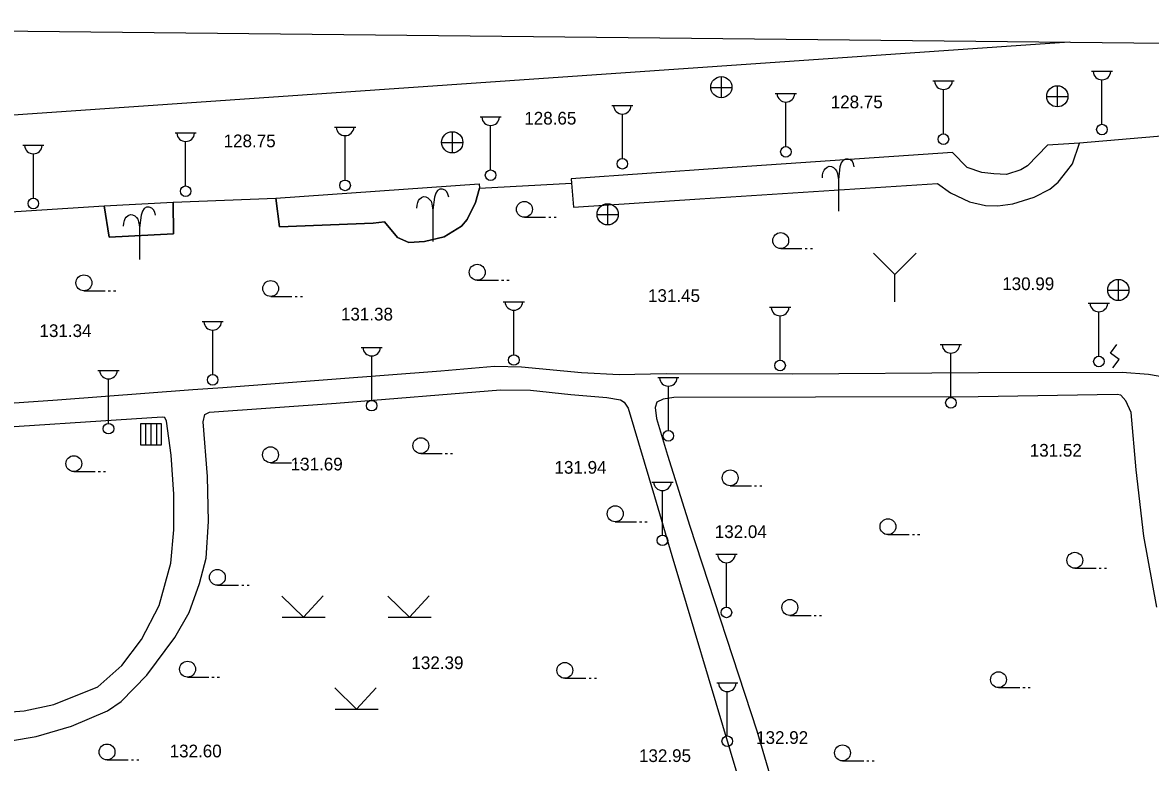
# Model space of a CAD drawing. Extents: x 419101 to 420177, y 4451541 to 4452254.
# Drawn here: x 419185.8 to 419292.2, y 4452175.9 to 4452245.8 of the extents above; entities that cross this region are included whole.
import ezdxf

# ---------------------------------------------------------------- set-up
doc = ezdxf.new("R2010")
doc.units = 0
doc.layers.add('0_ÖNERİ_LEJAND', color=7, linetype='Continuous')
doc.layers.add('3_HALİHAZIR', color=7, linetype='Continuous')

msp = doc.modelspace()

# ---------------------------------------------------------------- linework, layer by layer
at = {"layer": '0_ÖNERİ_LEJAND'}
msp.add_lwpolyline([(419108.72, 4452245.78), (420173.1, 4452234.54), (420165.77, 4451540.51), (419101.3, 4451551.75)], close=True, dxfattribs=at)
at = {"layer": '3_HALİHAZIR'}
for p, q in [((419251.71, 4452238.67), (419251.71, 4452240.67)), ((419271.64, 4452240.27), (419273.64, 4452240.27)), ((419286.6, 4452241.18), (419288.6, 4452241.18)), ((419287.6, 4452236.18), (419287.6, 4452240.37)), ((419250.69, 4452239.66), (419252.69, 4452239.66)), ((419272.64, 4452235.27), (419272.64, 4452239.46)), ((419283.41, 4452237.81), (419283.41, 4452239.81)), ((419256.78, 4452239.08), (419258.78, 4452239.08)), ((419257.78, 4452234.08), (419257.78, 4452238.27)), ((419282.39, 4452238.8), (419284.39, 4452238.8)), ((419241.35, 4452237.95), (419243.35, 4452237.95)), ((419242.35, 4452232.95), (419242.35, 4452237.15)), ((419215.19, 4452235.91), (419217.19, 4452235.91)), ((419228.92, 4452236.87), (419230.92, 4452236.87)), ((419229.92, 4452231.87), (419229.92, 4452236.06)), ((419200.15, 4452235.36), (419202.15, 4452235.36)), ((419216.19, 4452230.91), (419216.19, 4452235.11)), ((419226.31, 4452233.46), (419226.31, 4452235.46)), ((419185.78, 4452234.2), (419187.78, 4452234.2)), ((419201.15, 4452230.36), (419201.15, 4452234.56)), ((419225.29, 4452234.45), (419227.29, 4452234.45)), ((419186.78, 4452229.2), (419186.78, 4452233.4)), ((419240.98, 4452226.67), (419240.98, 4452228.67)), ((419233.11, 4452227.4), (419235.11, 4452227.4)), ((419235.41, 4452227.4), (419235.61, 4452227.4)), ((419235.91, 4452227.4), (419236.11, 4452227.4)), ((419239.96, 4452227.66), (419241.96, 4452227.66)), ((419257.29, 4452224.45), (419259.29, 4452224.45)), ((419259.59, 4452224.45), (419259.79, 4452224.45)), ((419260.09, 4452224.45), (419260.29, 4452224.45)), ((419268.06, 4452222.01), (419266.06, 4452224.01)), ((419268.06, 4452222.01), (419270.07, 4452224.01)), ((419228.66, 4452221.46), (419230.66, 4452221.46)), ((419230.96, 4452221.46), (419231.16, 4452221.46)), ((419231.46, 4452221.46), (419231.66, 4452221.46)), ((419268.06, 4452219.42), (419268.06, 4452222.01)), ((419289.16, 4452219.53), (419289.16, 4452221.53)), ((419191.55, 4452220.46), (419193.55, 4452220.46)), ((419193.85, 4452220.46), (419194.05, 4452220.46)), ((419194.35, 4452220.46), (419194.55, 4452220.46)), ((419209.17, 4452219.93), (419211.17, 4452219.93)), ((419211.47, 4452219.93), (419211.67, 4452219.93)), ((419211.97, 4452219.93), (419212.17, 4452219.93)), ((419288.14, 4452220.52), (419290.14, 4452220.52)), ((419231.11, 4452219.43), (419233.11, 4452219.43)), ((419256.23, 4452218.91), (419258.23, 4452218.91)), ((419286.31, 4452219.29), (419288.31, 4452219.29)), ((419232.11, 4452214.43), (419232.11, 4452218.63)), ((419257.23, 4452213.91), (419257.23, 4452218.1)), ((419287.31, 4452214.29), (419287.31, 4452218.48)), ((419202.7, 4452217.56), (419204.7, 4452217.56)), ((419203.7, 4452212.56), (419203.7, 4452216.75)), ((419217.7, 4452215.12), (419219.7, 4452215.12)), ((419272.35, 4452215.39), (419274.35, 4452215.39)), ((419218.7, 4452210.12), (419218.7, 4452214.31)), ((419273.35, 4452210.39), (419273.35, 4452214.58)), ((419192.87, 4452212.95), (419194.87, 4452212.95)), ((419193.87, 4452207.95), (419193.87, 4452212.15)), ((419245.69, 4452212.27), (419247.69, 4452212.27)), ((419246.69, 4452207.27), (419246.69, 4452211.46)), ((419198.88, 4452207.92), (419196.88, 4452207.92)), ((419196.88, 4452207.92), (419196.88, 4452205.92)), ((419198.88, 4452207.92), (419196.88, 4452207.92)), ((419196.88, 4452207.92), (419196.88, 4452205.92)), ((419197.39, 4452205.92), (419197.39, 4452207.92)), ((419197.88, 4452205.92), (419197.88, 4452207.92)), ((419198.43, 4452205.92), (419198.43, 4452207.92)), ((419198.88, 4452205.92), (419198.88, 4452207.92)), ((419198.88, 4452205.92), (419198.88, 4452207.92)), ((419196.88, 4452205.92), (419198.88, 4452205.92)), ((419196.88, 4452205.92), (419198.88, 4452205.92)), ((419223.34, 4452205.1), (419225.34, 4452205.1)), ((419225.64, 4452205.1), (419225.84, 4452205.1)), ((419226.14, 4452205.1), (419226.34, 4452205.1)), ((419209.15, 4452204.24), (419211.15, 4452204.24)), ((419211.45, 4452204.24), (419211.65, 4452204.24)), ((419211.95, 4452204.24), (419212.15, 4452204.24)), ((419190.6, 4452203.4), (419192.6, 4452203.4)), ((419192.9, 4452203.4), (419193.1, 4452203.4)), ((419193.4, 4452203.4), (419193.6, 4452203.4)), ((419245.13, 4452202.41), (419247.13, 4452202.41)), ((419252.52, 4452202.06), (419254.52, 4452202.06)), ((419254.82, 4452202.06), (419255.02, 4452202.06)), ((419255.32, 4452202.06), (419255.52, 4452202.06)), ((419246.13, 4452197.41), (419246.13, 4452201.6)), ((419241.68, 4452198.67), (419243.68, 4452198.67)), ((419243.98, 4452198.67), (419244.18, 4452198.67)), ((419244.48, 4452198.67), (419244.68, 4452198.67)), ((419267.41, 4452197.45), (419269.41, 4452197.45)), ((419269.71, 4452197.45), (419269.91, 4452197.45)), ((419270.21, 4452197.45), (419270.41, 4452197.45)), ((419251.17, 4452195.61), (419253.17, 4452195.61)), ((419252.17, 4452190.61), (419252.17, 4452194.81)), ((419285.04, 4452194.28), (419287.04, 4452194.28)), ((419287.34, 4452194.28), (419287.54, 4452194.28)), ((419287.84, 4452194.28), (419288.04, 4452194.28)), ((419204.14, 4452192.67), (419206.14, 4452192.67)), ((419206.44, 4452192.67), (419206.64, 4452192.67)), ((419206.94, 4452192.67), (419207.14, 4452192.67)), ((419212.28, 4452189.65), (419210.22, 4452191.64)), ((419212.28, 4452189.65), (419214.13, 4452191.66)), ((419222.28, 4452189.65), (419220.22, 4452191.64)), ((419222.28, 4452189.65), (419224.13, 4452191.66)), ((419210.26, 4452189.65), (419214.3, 4452189.65)), ((419220.26, 4452189.65), (419224.3, 4452189.65)), ((419258.15, 4452189.83), (419260.15, 4452189.83)), ((419260.45, 4452189.83), (419260.65, 4452189.83)), ((419260.95, 4452189.83), (419261.15, 4452189.83)), ((419201.33, 4452184), (419203.33, 4452184)), ((419203.63, 4452184), (419203.83, 4452184)), ((419204.13, 4452184), (419204.33, 4452184)), ((419236.92, 4452183.89), (419238.92, 4452183.89)), ((419239.22, 4452183.89), (419239.42, 4452183.89)), ((419239.72, 4452183.89), (419239.92, 4452183.89)), ((419217.28, 4452180.99), (419215.22, 4452182.98)), ((419217.28, 4452180.99), (419219.13, 4452183)), ((419251.25, 4452183.45), (419253.25, 4452183.45)), ((419277.84, 4452183.01), (419279.84, 4452183.01)), ((419280.14, 4452183.01), (419280.34, 4452183.01)), ((419280.64, 4452183.01), (419280.84, 4452183.01)), ((419252.25, 4452178.45), (419252.25, 4452182.64)), ((419215.26, 4452180.99), (419219.3, 4452180.99)), ((419193.73, 4452176.19), (419195.73, 4452176.19)), ((419196.03, 4452176.19), (419196.23, 4452176.19)), ((419196.53, 4452176.19), (419196.73, 4452176.19)), ((419263.12, 4452176.1), (419265.12, 4452176.1)), ((419265.42, 4452176.1), (419265.62, 4452176.1)), ((419265.92, 4452176.1), (419266.12, 4452176.1))]:
    msp.add_line(p, q, dxfattribs=at)
for points in [[(419284.52, 4452243.92), (419146.62, 4452234.38)], [(419293.94, 4452235.13), (419285.48, 4452234.41)], [(419209.65, 4452229.19), (419210, 4452226.5), (419218.83, 4452226.84), (419219.9, 4452226.98), (419221.14, 4452225.48), (419222.21, 4452225.03), (419223.68, 4452225.12), (419225.53, 4452225.54), (419227.18, 4452226.57), (419227.72, 4452227.2), (419228.51, 4452228.8), (419228.87, 4452230.15), (419237.55, 4452230.63), (419237.74, 4452228.37), (419249.66, 4452229.13), (419272.09, 4452230.59), (419273.31, 4452229.72), (419275.09, 4452228.85), (419276.6, 4452228.5), (419277.77, 4452228.47), (419279.2, 4452228.67), (419281.2, 4452229.3), (419282.69, 4452230.04), (419283.46, 4452230.72), (419284.3, 4452231.75), (419284.82, 4452232.44), (419285.48, 4452234.41)], [(419264.23, 4452232.15), (419264.16, 4452232.45), (419264.05, 4452232.67), (419263.89, 4452232.83), (419263.64, 4452232.9), (419263.4, 4452232.9), (419263.17, 4452232.79), (419263.01, 4452232.55), (419262.88, 4452232.17), (419262.73, 4452230.97)], [(419261.23, 4452231.11), (419261.24, 4452231.4), (419261.3, 4452231.67), (419261.38, 4452231.84), (419261.47, 4452231.97), (419261.66, 4452232.13), (419261.86, 4452232.22), (419262.07, 4452232.19), (419262.27, 4452232.1), (419262.43, 4452231.95), (419262.56, 4452231.79), (419262.64, 4452231.53), (419262.68, 4452231.3), (419262.73, 4452230.97), (419262.73, 4452227.97)], [(419225.97, 4452229.29), (419225.9, 4452229.59), (419225.79, 4452229.81), (419225.63, 4452229.97), (419225.38, 4452230.04), (419225.14, 4452230.04), (419224.91, 4452229.93), (419224.75, 4452229.69), (419224.62, 4452229.31), (419224.47, 4452228.11)], [(419146.52, 4452225.31), (419152.71, 4452225.75), (419166.47, 4452226.75), (419193.47, 4452228.47)], [(419193.47, 4452228.47), (419193.93, 4452225.53), (419199.99, 4452225.83), (419199.98, 4452228.83)], [(419199.98, 4452228.83), (419209.65, 4452229.19)], [(419222.97, 4452228.25), (419222.98, 4452228.54), (419223.04, 4452228.81), (419223.12, 4452228.98), (419223.21, 4452229.11), (419223.4, 4452229.27), (419223.6, 4452229.36), (419223.81, 4452229.33), (419224.01, 4452229.24), (419224.17, 4452229.09), (419224.3, 4452228.93), (419224.38, 4452228.67), (419224.42, 4452228.44), (419224.47, 4452228.11), (419224.47, 4452225.11)], [(419195.3, 4452226.55), (419195.31, 4452226.84), (419195.37, 4452227.11), (419195.45, 4452227.28), (419195.54, 4452227.41), (419195.73, 4452227.57), (419195.93, 4452227.66), (419196.14, 4452227.63), (419196.34, 4452227.54), (419196.5, 4452227.39), (419196.63, 4452227.23), (419196.71, 4452226.97), (419196.75, 4452226.74), (419196.8, 4452226.41), (419196.8, 4452223.41)], [(419198.3, 4452227.59), (419198.23, 4452227.89), (419198.12, 4452228.11), (419197.96, 4452228.27), (419197.71, 4452228.34), (419197.47, 4452228.34), (419197.24, 4452228.23), (419197.08, 4452227.99), (419196.95, 4452227.61), (419196.8, 4452226.41)], [(419288.61, 4452213.18), (419289.21, 4452213.99), (419288.4, 4452214.58), (419289, 4452215.39)], [(419201.83, 4452211.15), (419204.67, 4452211.33), (419225.21, 4452212.9), (419230.3, 4452213.34), (419232.85, 4452213.3), (419238.5, 4452212.76), (419242.06, 4452212.57), (419246.48, 4452212.66), (419258.37, 4452212.63), (419275.95, 4452212.76), (419289.51, 4452212.77), (419291.99, 4452212.6), (419293.63, 4452212.3)], [(419146.32, 4452206.22), (419150.63, 4452206.65), (419165.04, 4452208.17), (419177.23, 4452209.35), (419189.07, 4452210.16), (419201.83, 4452211.15)], [(419182.36, 4452177.61), (419187.05, 4452178.39), (419190.39, 4452179.38), (419193.79, 4452180.83), (419195.05, 4452181.69), (419197.49, 4452184.18), (419200.12, 4452187.74), (419201.47, 4452190.09), (419202.45, 4452192.83), (419203.08, 4452195.22), (419203.32, 4452198.7), (419203.21, 4452202.94), (419202.8, 4452208.11), (419202.95, 4452208.79), (419203.41, 4452209), (419215.36, 4452209.85), (419230.84, 4452211.11), (419233.68, 4452211.08), (419237.5, 4452210.69), (419240.9, 4452210.38), (419242.16, 4452210.18), (419242.53, 4452209.94), (419242.9, 4452209.37), (419245.37, 4452201.04), (419247.02, 4452195.49), (419258.01, 4452158.62)], [(419292.79, 4452190.61), (419291.56, 4452197.29), (419290.84, 4452203.58), (419290.36, 4452208.97), (419289.85, 4452210.09), (419289.39, 4452210.6), (419289.04, 4452210.68), (419275.92, 4452210.47), (419260.56, 4452210.41), (419247.2, 4452210.38), (419246.21, 4452210.24), (419245.61, 4452209.94), (419245.46, 4452209.44), (419245.58, 4452208.4), (419246.61, 4452204.94), (419248.73, 4452198.24), (419255.05, 4452178.94), (419260.31, 4452161.01)], [(419161.88, 4452199.17), (419163.03, 4452195.96), (419166, 4452187.68), (419166.51, 4452186.58), (419167.54, 4452185.42), (419169.47, 4452183.6), (419171.9, 4452182.48), (419175.61, 4452181.17), (419178.62, 4452180.55), (419181.44, 4452180.46), (419185.9, 4452180.83), (419188.71, 4452181.42), (419192.85, 4452183.09), (419195.14, 4452185.09), (419196.97, 4452187.56), (419198.64, 4452190.77), (419199.75, 4452194.77), (419200.02, 4452197.9), (419200.02, 4452201.28), (419199.77, 4452204.94), (419199.34, 4452208.16), (419199.17, 4452208.5), (419198.92, 4452208.53), (419179.62, 4452207.29)]]:
    msp.add_lwpolyline(points, dxfattribs=at)
for points in [[(419285.48, 4452234.41), (419282.45, 4452234.22), (419280.59, 4452232.25), (419279.95, 4452231.88), (419278.6, 4452231.43), (419277.41, 4452231.49), (419276.26, 4452231.62), (419274.87, 4452232.09), (419273.49, 4452233.52), (419251.81, 4452232.05), (419237.52, 4452231.02), (419237.55, 4452230.63), (419237.74, 4452228.37), (419249.66, 4452229.13), (419249.66, 4452229.13), (419272.09, 4452230.59), (419273.31, 4452229.72), (419275.09, 4452228.85), (419276.6, 4452228.5), (419277.77, 4452228.47), (419279.2, 4452228.67), (419281.2, 4452229.3), (419282.69, 4452230.04), (419283.46, 4452230.72), (419284.3, 4452231.75), (419284.82, 4452232.44), (419285.48, 4452234.41)], [(419209.65, 4452229.19), (419228.83, 4452230.55), (419228.87, 4452230.15), (419228.51, 4452228.8), (419227.72, 4452227.2), (419227.18, 4452226.57), (419225.53, 4452225.54), (419223.68, 4452225.12), (419222.21, 4452225.03), (419221.14, 4452225.48), (419219.9, 4452226.98), (419218.83, 4452226.84), (419210, 4452226.5)], [(419193.47, 4452228.47), (419199.98, 4452228.83), (419199.99, 4452225.83), (419193.93, 4452225.53)]]:
    msp.add_lwpolyline(points, close=True, dxfattribs=at)
for centre, radius in [((419251.69, 4452239.68), 1), ((419283.39, 4452238.82), 1), ((419287.6, 4452235.68), 0.5), ((419226.3, 4452234.47), 1), ((419272.64, 4452234.77), 0.5), ((419257.78, 4452233.58), 0.5), ((419242.35, 4452232.45), 0.5), ((419229.92, 4452231.37), 0.5), ((419216.19, 4452230.41), 0.5), ((419201.15, 4452229.86), 0.5), ((419186.78, 4452228.7), 0.5), ((419233.11, 4452228.15), 0.75), ((419240.96, 4452227.68), 1), ((419257.29, 4452225.2), 0.75), ((419228.66, 4452222.21), 0.75), ((419191.55, 4452221.21), 0.75), ((419209.17, 4452220.68), 0.75), ((419289.14, 4452220.54), 1), ((419232.11, 4452213.93), 0.5), ((419257.23, 4452213.41), 0.5), ((419287.31, 4452213.79), 0.5), ((419203.7, 4452212.06), 0.5), ((419273.35, 4452209.89), 0.5), ((419218.7, 4452209.62), 0.5), ((419193.87, 4452207.45), 0.5), ((419246.69, 4452206.77), 0.5), ((419223.34, 4452205.85), 0.75), ((419209.15, 4452204.99), 0.75), ((419190.6, 4452204.15), 0.75), ((419252.52, 4452202.81), 0.75), ((419241.68, 4452199.42), 0.75), ((419267.41, 4452198.2), 0.75), ((419246.13, 4452196.91), 0.5), ((419285.04, 4452195.03), 0.75), ((419204.14, 4452193.42), 0.75), ((419258.15, 4452190.58), 0.75), ((419252.17, 4452190.11), 0.5), ((419201.33, 4452184.75), 0.75), ((419236.92, 4452184.64), 0.75), ((419277.84, 4452183.76), 0.75), ((419252.25, 4452177.95), 0.5), ((419193.73, 4452176.94), 0.75), ((419263.12, 4452176.85), 0.75)]:
    msp.add_circle(centre, radius, dxfattribs=at)
for centre in [(419272.64, 4452240.3), (419287.6, 4452241.21), (419257.78, 4452239.11), (419242.35, 4452237.98), (419216.19, 4452235.94), (419229.92, 4452236.9), (419201.15, 4452235.39), (419186.78, 4452234.23), (419232.11, 4452219.46), (419257.23, 4452218.94), (419287.31, 4452219.32), (419203.7, 4452217.59), (419218.7, 4452215.15), (419273.35, 4452215.42), (419193.87, 4452212.98), (419246.69, 4452212.3), (419246.13, 4452202.44), (419252.17, 4452195.64), (419252.25, 4452183.48)]:
    msp.add_arc(centre, 0.837, 183.298, 356.9072, dxfattribs=at)

# ---------------------------------------------------------------- texts
for s, p in [('128.75 ', (419262.01, 4452237.69)), ('128.65 ', (419233.1, 4452236.15)), ('128.75 ', (419204.73, 4452234.01)), ('130.99 ', (419278.19, 4452220.53)), ('131.45 ', (419244.77, 4452219.41)), ('131.38 ', (419215.8, 4452217.66)), ('131.34 ', (419187.36, 4452216.1)), ('131.52 ', (419280.79, 4452204.81)), ('131.69 ', (419211.06, 4452203.51)), ('131.94 ', (419235.95, 4452203.2)), ('132.04 ', (419251.07, 4452197.13)), ('132.39 ', (419222.45, 4452184.76)), ('132.92 ', (419254.97, 4452177.7)), ('132.60 ', (419199.64, 4452176.43)), ('132.95 ', (419243.92, 4452175.99))]:
    msp.add_text(s, height=1.2, rotation=359.998, dxfattribs=at).set_placement(p)

doc.saveas('drawing.dxf')
